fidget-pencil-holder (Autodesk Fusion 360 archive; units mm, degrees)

design "Fidget Pencil Holder"
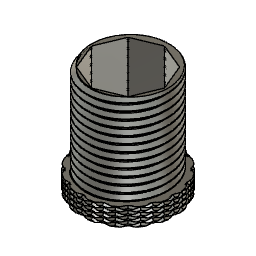
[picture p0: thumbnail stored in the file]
sketch "Sketch1" plane through (0, 0, 0) normal (0, 0, 1) x axis (1, 0, 0)
  line L1 (23.3345, 23.3345) -> (33, 0)
  line L2 (0, 33) -> (23.3345, 23.3345)
  line L3 (-23.3345, 23.3345) -> (0, 33)
  line L4 (-33, 0) -> (-23.3345, 23.3345)
  line L5 (-23.3345, -23.3345) -> (-33, 0)
  line L6 (0, -33) -> (-23.3345, -23.3345)
  line L7 (23.3345, -23.3345) -> (0, -33)
  line L8 (33, 0) -> (23.3345, -23.3345)
  circle C1 centre (0, 0) radius 35
  point P1 (0, 0)
  point P10 (0, 0)
  point P11 (0, 0)
  point P2 (33, 0)
  coincident P1 P10
  coincident P1 P11
  dimension "d1" distance P2 P10 = 33
extrude "Extrude1" new body sketch "Sketch1" along normal blind 3 bodies "Pen Holder"
extrude "Extrude2" add sketch "Sketch1" along normal blind 90
sketch "Sketch2" plane through (0, 0, 0) normal (0, 0, 1) x axis (1, 0, 0)
  circle C1 centre (0, 0) radius 35
  circle C2 centre (0, 0) radius 40
  point P1 (0, 0)
  point P2 (0, 0)
  point P3 (0, 0)
  coincident P1 P2
  coincident P1 P3
offset_faces "OffsetFaces1" distance 1.8
thread "Thread1"
extrude "Extrude3" new body sketch "Sketch2" along normal blind 15 bodies "Ring"
thread "Thread2"
sketch "Sketch3" plane through (0, 0, 0) normal (0, 0, 1) x axis (1, 0, 0)
  circle C1 centre (0, 0) radius 40
  circle C2 centre (0, 0) radius 45
  point P1 (0, 0)
  point P2 (0, 0)
  point P3 (-40, 0)
  point P4 (0, 0)
  coincident P1 P2
  coincident C1 P3
  coincident P1 P4
extrude "Extrude4" new body sketch "Sketch3" along normal blind 15
copy_paste_bodies "CopyPasteBodies1"
move "Move1"
coil_primitive "CoilPrimitive1" Diameter 80 SectionSize 2 TaperAngle 0 Revolutions 0.25 Height 15
circular_pattern "C-Pattern1" countU 16 TotalAngle 360
combine "Combine1"
coil_primitive "CoilPrimitive2" Diameter 80 SectionSize 2 TaperAngle 0 Revolutions 0.25 Height 15
circular_pattern "C-Pattern2" countU 16 TotalAngle 360
combine "Combine2"
combine "Combine3"
extrude "Extrude5" add sketch "Sketch1" along normal blind 2
offset_faces "OffsetFaces2" distance -0.2
extrude "Extrude6" add sketch "Sketch1" along normal blind 2
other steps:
base_feature "Base Feature" bodies "CCW"
named bodies: "Pen Holder", "Ring", "CCW"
